// Mitsubishi GX Works2 project: 14.控制方式选择   PLC: FX3U/FX3UC

PROGRAM MAIN
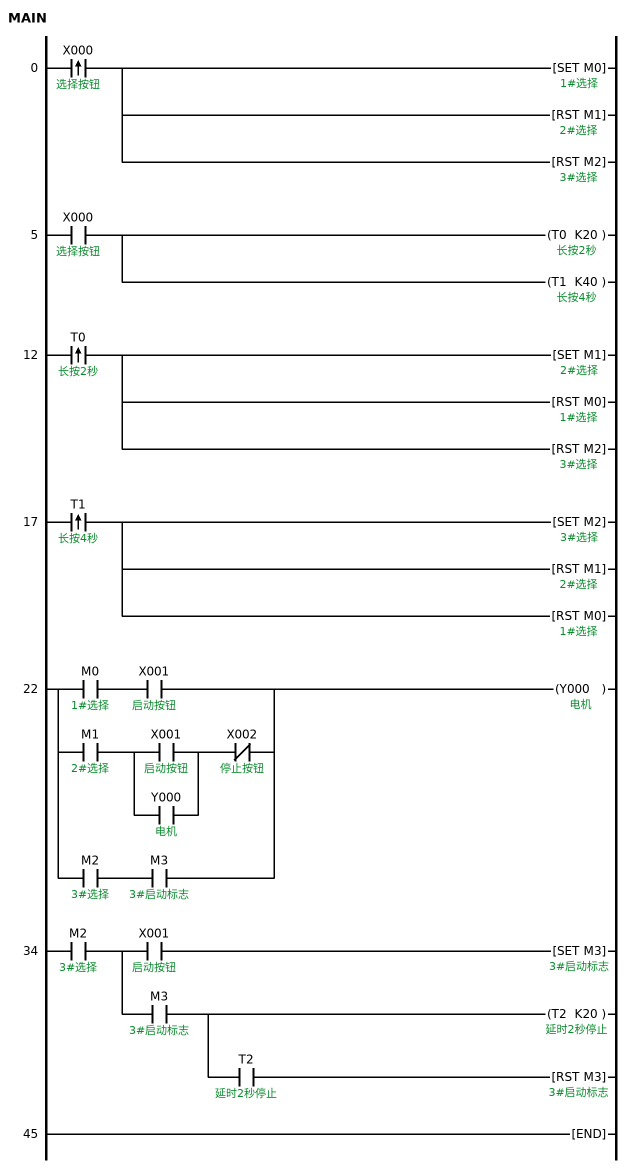
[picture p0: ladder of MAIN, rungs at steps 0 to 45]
0     LDP     X000  ; 选择按钮
      SET     M0  ; 1#选择
      RST     M1  ; 2#选择
      RST     M2  ; 3#选择
5     LD      X000  ; 选择按钮
      OUT     T0 K20  ; 长按2秒
      OUT     T1 K40  ; 长按4秒
12    LDP     T0  ; 长按2秒
      SET     M1  ; 2#选择
      RST     M0  ; 1#选择
      RST     M2  ; 3#选择
17    LDP     T1  ; 长按4秒
      SET     M2  ; 3#选择
      RST     M1  ; 2#选择
      RST     M0  ; 1#选择
22    LD      M0  ; 1#选择
      AND     X001  ; 启动按钮
      LD      M1  ; 2#选择
      LD      X001  ; 启动按钮
      OR      Y000  ; 电机
      ANB
      ANI     X002  ; 停止按钮
      ORB
      LD      M2  ; 3#选择
      AND     M3  ; 3#启动标志
      ORB
      OUT     Y000  ; 电机
34    LD      M2  ; 3#选择
      MPS
      AND     X001  ; 启动按钮
      SET     M3  ; 3#启动标志
      MPP
      AND     M3  ; 3#启动标志
      OUT     T2 K20  ; 延时2秒停止
      AND     T2  ; 延时2秒停止
      RST     M3  ; 3#启动标志
45    END
END_PROGRAM
